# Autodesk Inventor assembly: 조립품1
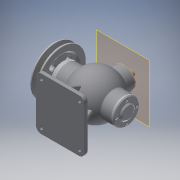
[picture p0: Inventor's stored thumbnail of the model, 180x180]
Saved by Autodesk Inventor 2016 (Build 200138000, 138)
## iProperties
Created: 2017-01
Part Number: 조립품1
Material: 일반
Document SubType Name: Assembly
Designer: Administrator
Author: Administrator
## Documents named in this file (19)
- C:\Users\Administrator\Desktop\470130V1001\조립품1.iam
- C:\Users\Administrator\Desktop\470130V1001\470130V1001\본체.ipt
- C:\Users\Administrator\Desktop\470130V1001\470130V1001\편심축.ipt
- C:\Users\Administrator\Desktop\470130V1001\470130V1001\베어링- 6202.ipt
- KS B 2023 - 6202 - 15 x 35 x 11 - 7.8.ipt
- C:\Users\Administrator\Desktop\470130V1001\470130V1001\부시.ipt
- C:\Users\Administrator\Desktop\470130V1001\470130V1001\앞커버.ipt
- C:\Users\Administrator\Desktop\470130V1001\470130V1001\오일실 15 30 7.ipt
- C:\Users\Administrator\Desktop\470130V1001\470130V1001\멈춤링- 15 x 1.ipt
- C:\Users\Administrator\Desktop\470130V1001\470130V1001\멈춤링- 35x1.6.ipt
- KS B 1336 - 35x1.6.ipt
- C:\Users\Administrator\Desktop\470130V1001\470130V1001\뒤커버.ipt
- C:\Users\Administrator\Desktop\470130V1001\470130V1001\볼트 M4 x 16.ipt
- C:\Users\Administrator\Desktop\470130V1001\470130V1001\볼트 M4 x 12.ipt
- C:\Users\Administrator\Desktop\470130V1001\470130V1001\V-벨트풀리.ipt
- C:\Users\Administrator\Desktop\470130V1001\470130V1001\너트 M8.ipt
- C:\Users\Administrator\Desktop\470130V1001\470130V1001\키 4 x 4 x 12.ipt
- C:\Users\Administrator\Desktop\470130V1001\470130V1001\상부커버.ipt
- C:\Users\Administrator\Desktop\470130V1001\470130V1001\슬라이드.ipt
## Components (16 placed, 5 different names)
1. KS B 2023 - 6202 - 15 x 35 x 11 - 7.8:1
2. KS B 1336 - 35x1.6:1
3. KS B 2023 - 6202 - 15 x 35 x 11 - 7.8:2
4. V-벨트풀리:1
5. ISO 4762 M4 x 16:1
6. ISO 4762 M4 x 16:2
7. ISO 4762 M4 x 16:3
8. ISO 4762 M4 x 16:4
9. KS B 1021 - 에 따름 ISO 1207 - 미터 A  M 4 x 12:1
10. KS B 1021 - 에 따름 ISO 1207 - 미터 A  M 4 x 12:2
11. KS B 1021 - 에 따름 ISO 1207 - 미터 A  M 4 x 12:3
12. KS B 1021 - 에 따름 ISO 1207 - 미터 A  M 4 x 12:4
13. KS B 1021 - 에 따름 ISO 1207 - 미터 A  M 4 x 12:5
14. KS B 1021 - 에 따름 ISO 1207 - 미터 A  M 4 x 12:6
15. KS B 1021 - 에 따름 ISO 1207 - 미터 A  M 4 x 12:7
16. KS B 1021 - 에 따름 ISO 1207 - 미터 A  M 4 x 12:8
